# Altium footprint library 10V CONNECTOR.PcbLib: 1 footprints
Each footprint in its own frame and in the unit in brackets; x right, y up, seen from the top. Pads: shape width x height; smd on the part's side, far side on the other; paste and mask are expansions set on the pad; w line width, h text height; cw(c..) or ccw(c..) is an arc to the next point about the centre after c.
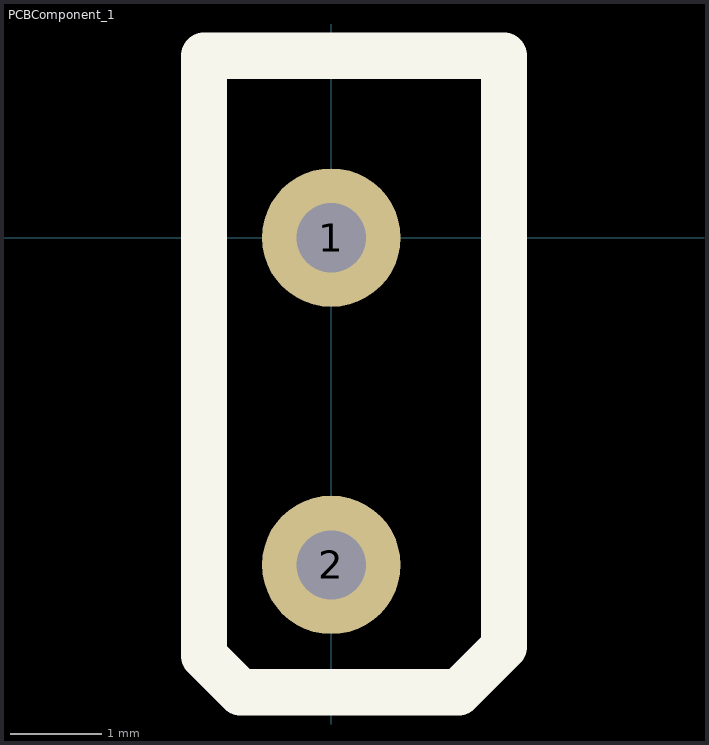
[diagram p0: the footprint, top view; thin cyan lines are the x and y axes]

## PCBComponent_1 [mil]
pads (2):
  round 60 hole 30: 1(0,0) 2(0,-141.73)
Top Overlay:
  lines w20: -55.12,-181.1 -39.37,-196.85 55.12,-196.85 74.8,-177.17 74.8,78.74 -55.12,78.74 -55.12,-181.1
M5 Assembly Top:
  text ".Designator" at 0,-3.94 h40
